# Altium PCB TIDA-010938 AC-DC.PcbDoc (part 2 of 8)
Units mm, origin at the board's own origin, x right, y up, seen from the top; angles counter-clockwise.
Board outline 280 x 180.15 mm, 4 copper layers (Top Layer, Layer 1, Layer 2, Bottom Layer), stack 1.787 mm thick; 723 components, 427 nets, 2244 pads, 2295 vias.
Unrouted connection lines stored in the file: 17.
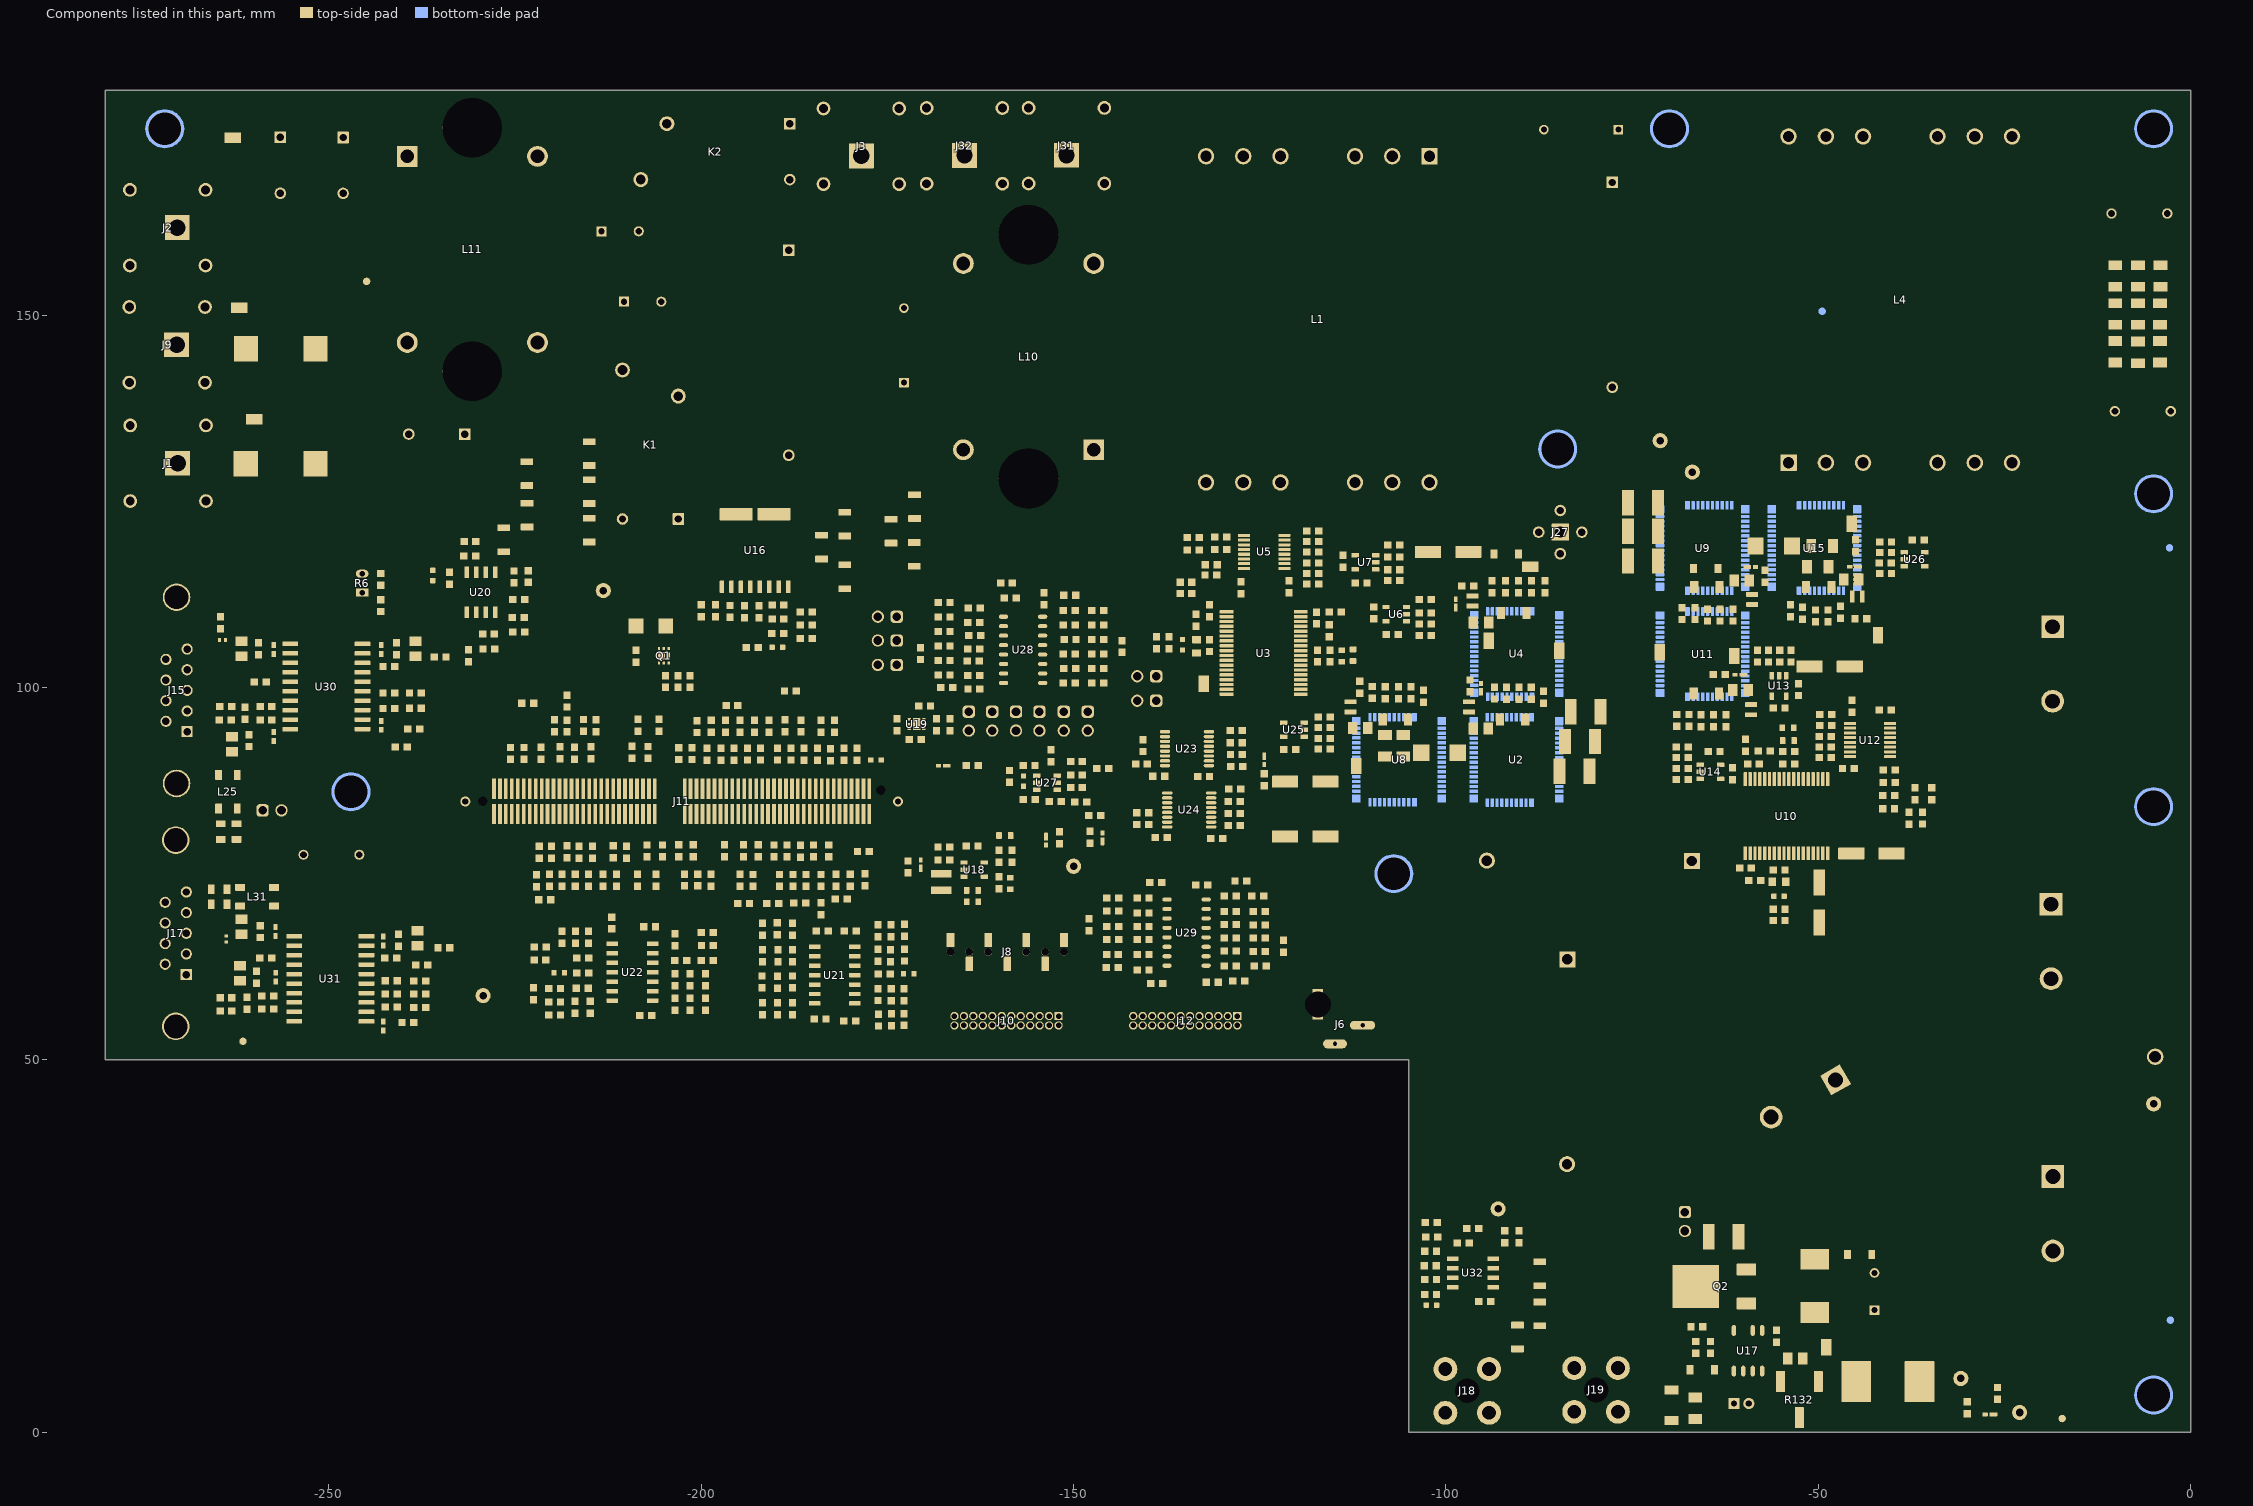
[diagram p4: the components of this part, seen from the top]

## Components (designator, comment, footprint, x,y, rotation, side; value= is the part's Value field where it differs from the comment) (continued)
R111 "TNPV12061M00BEEN" TNPV1206 -180.717,121.92 r270 top value=1.00Meg
R112 "TNPV12061M00BEEN" TNPV1206 -183.825,118.847 r270 top value=1.00Meg
R113 "TNPV12061M00BEEN" TNPV1206 -180.717,114.859 r270 top value=1.00Meg
R114 "PTCEL13R600LBE" FP-PTCEL13R600LBE_RADIAL-MFG -210.867,161.239 r0 top value=60Ω
R115 "RC0603JR-075K6L" 0603 -45,119 r270 top value=5.6k
R116 "TNPV12061M00BEEN" TNPV1206 -215,131.4 r270 top value=1.00Meg
R117 "TNPV12061M00BEEN" TNPV1206 -215,126.3 r270 top value=1.00Meg
R118 "TNPV12061M00BEEN" TNPV1206 -215.033,121.132 r270 top value=1.00Meg
R119 "RT0603BRD077K32L" 0603 -174.55,63.975 r90 top value=7.32k
R120 "RG1608P-560-B-T5" 0603 -224.469,111.785 r0 top value=56
R121 "RG1608P-560-B-T5" 0603 -231.25,104.254 r270 top value=56
R122 "TNPV12061M00BEEN" TNPV1206 -171.345,124.282 r270 top value=1.00Meg
R123 "TNPV12061M00BEEN" TNPV1206 -174.494,120.98 r270 top value=1.00Meg
R124 "TNPV12061M00BEEN" TNPV1206 -171.386,117.856 r270 top value=1.00Meg
R125 "RG1608P-103-B-T5" 0603 -237.5,62.75 r0 top value=10.0k
R126 "RG1608P-103-B-T5" 0603 -258.448,63.698 r0 top value=10.0k
R127 "TNPV12061M00BEEN" TNPV1206 -223.4,128.7 r270 top value=1.00Meg
R128 "TNPV12061M00BEEN" TNPV1206 -223.364,123.139 r270 top value=1.00Meg
R129 "TNPV12061M00BEEN" TNPV1206 -226.513,119.837 r270 top value=1.00Meg
R130 "RG1608P-103-B-T5" 0603 -231.022,119.58 r0 top value=10.0k
R131 "RG1608P-103-B-T5" 0603 -228.539,107.185 r0 top value=10.0k
R132 "3269W-1-104LF" FP-3269W-1-104LF_SMD-MFG -52.553,4.401 r180 top
R133 "RG1608P-103-B-T5" 0603 -101.914,26.251 r0 top value=10.0k
R134 "RG1608P-560-B-T5" 0603 -96.43,27.381 r180 top value=56
R135 "RG1608P-103-B-T5" 0603 -101.99,28.194 r180 top value=10.0k
R136 "RT0603BRD077K32L" 0603 -221.625,63.4 r180 top value=7.32k
R137 "RT0603BRD077K32L" 0603 -172.7,64.075 r270 top value=7.32k
R138 "RT0603BRD077K32L" 0603 -172.7,67.4 r270 top value=7.32k
R139 "RT0603BRD077K32L" 0603 -221.597,65.173 r0 top value=7.32k
R140 "RG1608P-560-B-T5" 0603 -180.019,55.22 r180 top value=56
R141 "RG1608P-560-B-T5" 0603 -211.998,68.379 r90 top value=56
R142 "RT0603BRD077K32L" 0603 -174.525,67.35 r270 top value=7.32k
R143 "RT0603BRD077K32L" 0603 -218.657,66.476 r270 top value=7.32k
R144 "RG1608P-560-B-T5" 0603 -163.242,106.985 r180 top value=56
R145 "RT0603BRD077K32L" 0603 -216.879,66.476 r270 top value=7.32k
R146 "RG1608P-560-B-T5" 0603 -163.458,103.556 r180 top value=56
R147 "RG1608P-103-B-T5" 0603 -219.673,59.576 r180 top value=10.0k
R148 "RG1608P-560-B-T5" 0603 -163.369,99.797 r180 top value=56
R149 "RG1608P-103-B-T5" 0603 -222.5,58.894 r270 top value=10.0k
R150 "RG1608P-560-B-T5" 0603 -179.968,67.302 r180 top value=56
R151 "RG1608P-560-B-T5" 0603 -219.673,56.02 r180 top value=56
R152 "RG1608P-560-B-T5" 0603 -159,114 r180 top value=56
R153 "RG1608P-103-B-T5" 0603 -219.673,57.798 r180 top value=10.0k
R154 "RG1608P-560-B-T5" 0603 -150.529,102.565 r0 top value=56
R155 "RG1608P-103-B-T5" 0603 -216.912,57.078 r270 top value=10.0k
R156 "RT0603BRD077K32L" 0603 -201.467,60.78 r90 top value=7.32k
R157 "RG1608P-103-B-T5" 0603 -189.675,63.975 r270 top value=10.0k
R158 "RG1608P-103-B-T5" 0603 -191.769,63.981 r90 top value=10.0k
R159 "RT0603BRD077K32L" 0603 -199.435,60.78 r270 top value=7.32k
R160 "RG1608P-560-B-T5" 0603 -183.74,67.3 r0 top value=56
R161 "RG1608P-560-B-T5" 0603 -207.426,55.933 r180 top value=56
R162 "RG1608P-103-B-T5" 0603 -191.769,67.537 r90 top value=10.0k
R163 "RT0603BRD077K32L" 0603 -199.435,57.478 r90 top value=7.32k
R164 "RG1608P-103-B-T5" 0603 -189.775,67.6 r90 top value=10.0k
R165 "RT0603BRD077K32L" 0603 -201.467,57.478 r90 top value=7.32k
R166 "RG1608P-103-B-T5" 0603 -199.143,65.352 r180 top value=10.0k
R167 "RG1608P-103-B-T5" 0603 -189.725,60.425 r270 top value=10.0k
R168 "RG1608P-103-B-T5" 0603 -191.802,60.467 r90 top value=10.0k
R169 "RG1608P-560-B-T5" 0603 -184.032,55.472 r0 top value=56
R170 "RG1608P-560-B-T5" 0603 -203.499,66.114 r90 top value=56
R171 "RG1608P-103-B-T5" 0603 -191.769,56.869 r270 top value=10.0k
R172 "RG1608P-103-B-T5" 0603 -199.181,63.32 r0 top value=10.0k
R173 "RG1608P-103-B-T5" 0603 -189.737,56.869 r270 top value=10.0k
R174 "RCS06030000Z0EA" 0603 -223.787,91.139 r90 top value=0
R175 "RG1608P-560-B-T5" 0603 -150.466,106.426 r0 top value=56
R176 "RCS06030000Z0EA" 0603 -215.8,94.9 r270 top value=0
R177 "RCS06030000Z0EA" 0603 -128.15,94.225 r180 top value=0
R178 "RCS06030000Z0EA" 0603 -216.975,91.175 r270 top value=0
R179 "RCS06030000Z0EA" 0603 -221.501,91.177 r90 top value=0
R180 "RCS06030000Z0EA" 0603 -218.025,94.825 r270 top value=0
R181 "RCS06030000Z0EA" 0603 -218.95,91.225 r270 top value=0
R182 "RCS06030000Z0EA" 0603 -220.375,74.1 r270 top value=0
R183 "RCS06030000Z0EA" 0603 -220.075,77.9 r270 top value=0
R184 "RCS06030000Z0EA" 0603 -218.025,77.925 r270 top value=0
R185 "ERJ-8ENF1693V" 1206 -4.155,150.146 r270 top value=169k
R186 "RCS06030000Z0EA" 0603 -215.118,74.129 r90 top value=0
R187 "RCS06030000Z0EA" 0603 -214.585,77.901 r90 top value=0
R188 "RCS06030000Z0EA" 0603 -213.153,74.116 r90 top value=0
R189 "RCS06030000Z0EA" 0603 -211.791,77.939 r90 top value=0
R190 "RCS06030000Z0EA" 0603 -208.55,74.125 r90 top value=0
R191 "RCS06030000Z0EA" 0603 -207.1,91.275 r90 top value=0
R192 "RCS06030000Z0EA" 0603 -207.244,78.051 r90 top value=0
R193 "RCS06030000Z0EA" 0603 -205.65,94.925 r90 top value=0
R194 "RCS06030000Z0EA" 0603 -209.25,91.3 r270 top value=0
R195 "RCS06030000Z0EA" 0603 -201.05,78.075 r270 top value=0
R196 "RCS06030000Z0EA" 0603 -208.45,94.925 r270 top value=0
R197 "RCS06030000Z0EA" 0603 -200.45,74.15 r270 top value=0
R198 "RCS06030000Z0EA" 0603 -206.05,74.125 r90 top value=0
R199 "RCS06030000Z0EA" 0603 -205.2,78.05 r90 top value=0
R200 "RCS06030000Z0EA" 0603 -203,78.075 r90 top value=0
R201 "RCS06030000Z0EA" 0603 -202.225,74.15 r90 top value=0
R202 "RCS06030000Z0EA" 0603 -128.35,86.35 r180 top value=0
R203 "RCS06030000Z0EA" 0603 -198.69,74.125 r90 top value=0
R204 "RCS06030000Z0EA" 0603 -201.219,91.126 r90 top value=0
R205 "RCS06030000Z0EA" 0603 -196.83,78.089 r90 top value=0
R206 "RCS06030000Z0EA" 0603 -198.641,94.798 r90 top value=0
R207 "RCS06030000Z0EA" 0603 -197.338,91.026 r90 top value=0
R208 "RCS06030000Z0EA" 0603 -196.699,94.776 r90 top value=0
R209 "RCS06030000Z0EA" 0603 -195.56,91.026 r90 top value=0
R210 "RCS06030000Z0EA" 0603 -194.325,78.1 r90 top value=0
R211 "RCS06030000Z0EA" 0603 -194.758,94.776 r90 top value=0
R212 "RCS06030000Z0EA" 0603 -193.02,74.091 r90 top value=0
R213 "RCS06030000Z0EA" 0603 -193.782,91.064 r90 top value=0
R214 "RCS06030000Z0EA" 0603 -192.325,78.1 r90 top value=0
R215 "RCS06030000Z0EA" 0603 -192.816,94.798 r90 top value=0
R216 "RCS06030000Z0EA" 0603 -192.004,91.064 r90 top value=0
R217 "RCS06030000Z0EA" 0603 -190.226,78.051 r90 top value=0
R218 "RCS06030000Z0EA" 0603 -190.875,94.775 r90 top value=0
R219 "RCS06030000Z0EA" 0603 -189.464,74.091 r90 top value=0
R220 "RCS06030000Z0EA" 0603 -189.718,91.064 r90 top value=0
R221 "RCS06030000Z0EA" 0603 -188.448,78.051 r90 top value=0
R222 "RCS06030000Z0EA" 0603 -188.75,94.85 r90 top value=0
R223 "RCS06030000Z0EA" 0603 -187.686,74.091 r90 top value=0
R224 "RCS06030000Z0EA" 0603 -187.94,91.064 r90 top value=0
R225 "RCS06030000Z0EA" 0603 -186.67,78.013 r90 top value=0
R226 "RCS06030000Z0EA" 0603 -186.609,94.825 r90 top value=0
R227 "RCS06030000Z0EA" 0603 -185.908,74.091 r90 top value=0
R228 "RCS06030000Z0EA" 0603 -186.162,91.026 r90 top value=0
R229 "RCS06030000Z0EA" 0603 -184.892,78.051 r90 top value=0
R230 "RCS06030000Z0EA" 0603 -184.384,91.026 r90 top value=0
R231 "RCS06030000Z0EA" 0603 -183.876,74.091 r90 top value=0
R232 "RCS06030000Z0EA" 0603 -183.876,94.798 r90 top value=0
R233 "RCS06030000Z0EA" 0603 -182.86,78.051 r90 top value=0
R234 "RCS06030000Z0EA" 0603 -182.606,90.988 r90 top value=0
R235 "ERJ-8ENF1693V" 1206 -7.108,150.146 r270 top value=169k
R236 "RCS06030000Z0EA" 0603 -182.098,94.798 r90 top value=0
R237 "RG1608P-103-B-T5" 0603 -102.8,107 r180 top value=10.0k
R238 "RG1608P-103-B-T5" 0603 -102.071,24.311 r180 top value=10.0k
R239 "RG1608P-103-B-T5" 0603 -102.091,22.37 r180 top value=10.0k
R240 "RCS06030000Z0EA" 0603 -127.525,74.025 r180 top value=0
R241 "RCS06030000Z0EA" 0603 -150.5,112.375 r180 top value=0
R242 "RCS06030000Z0EA" 0603 -121.8,65.275 r270 top value=0
R243 "RCS06030000Z0EA" 0603 -143.5,105.5 r270 top value=0
R244 "RCS06030000Z0EA" 0603 -127.827,60.598 r180 top value=0
R245 "RCS06030000Z0EA" 0603 -158.5,112 r180 top value=0
R246 "RCS06030000Z0EA" 0603 -138.825,60.25 r180 top value=0
R247 "RCS06030000Z0EA" 0603 -167,100 r180 top value=0
R248 "RCS06030000Z0EA" 0603 -147.9,68.125 r270 top value=0
R249 "RCS06030000Z0EA" 0603 -170.55,104.55 r270 top value=0
R250 "RCS06030000Z0EA" 0603 -138.975,73.825 r0 top value=0
R252 "RG1608P-103-B-T5" 0603 -149.6,86.55 r180 top value=10.0k
R253 "RG1608P-103-B-T5" 0603 -128.983,72.001 r180 top value=10.0k
R254 "RG1608P-103-B-T5" 0603 -150.553,110.312 r180 top value=10.0k
R256 "RG1608P-103-B-T5" 0603 -149.6,88.25 r180 top value=10.0k
R259 "RG1608P-560-B-T5" 0603 -140.667,69.715 r180 top value=56
R260 "RG1608P-560-B-T5" 0603 -167.385,109.463 r0 top value=56
R263 "RG1608P-560-B-T5" 0603 -144.731,71.747 r0 top value=56
R264 "RG1608P-560-B-T5" 0603 -140.667,66.159 r180 top value=56
R265 "RG1608P-560-B-T5" 0603 -167.385,105.58 r0 top value=56
R267 "RG1608P-560-B-T5" 0603 -144.731,67.937 r0 top value=56
R268 "RG1608P-560-B-T5" 0603 -167.385,101.697 r0 top value=56
R270 "RG1608P-560-B-T5" 0603 -144.769,64.127 r0 top value=56
R272 "RG1608P-560-B-T5" 0603 -140.667,62.095 r180 top value=56
R273 "RG1608P-560-B-T5" 0603 -146.743,100.602 r180 top value=56
R274 "RG1608P-560-B-T5" 0603 -124.935,62.603 r180 top value=56
R276 "RG1608P-560-B-T5" 0603 -146.743,104.485 r180 top value=56
R278 "RG1608P-560-B-T5" 0603 -125.049,66.344 r180 top value=56
R279 "RG1608P-560-B-T5" 0603 -131.4,60.425 r0 top value=56
R280 "RT0603DRE0759R7L" 0603 -258.41,95.645 r0 top value=59.7
R281 "RG1608P-560-B-T5" 0603 -146.743,108.368 r180 top value=56
R282 "RG1608P-560-B-T5" 0603 -125.049,69.9 r180 top value=56
R284 "RG1608P-560-B-T5" 0603 -128.983,64.602 r0 top value=56
R286 "RG1608P-560-B-T5" 0603 -128.983,68.158 r0 top value=56
R287 "RT0603DRE0759R7L" 0603 -258.41,97.423 r180 top value=59.7
R288 "RT0603DRE0759R7L" 0603 -258.152,56.82 r0 top value=59.7
R289 "RT0603DRE0759R7L" 0603 -258.19,58.598 r180 top value=59.7
R290 "ERJ-8ENF1693V" 1206 -10.156,150.146 r270 top value=169k
R291 "ERJ-8ENF1693V" 1206 -10.156,155.226 r270 top value=169k
R297 "RG1608P-103-B-T5" 0603 -146.743,110.31 r180 top value=10.0k
R298 "RG1608P-103-B-T5" 0603 -146.743,106.427 r180 top value=10.0k
R299 "RG1608P-103-B-T5" 0603 -146.743,102.544 r180 top value=10.0k
R300 "RG1608P-103-B-T5" 0603 -167.385,103.639 r0 top value=10.0k
R301 "RG1608P-103-B-T5" 0603 -167.385,107.522 r0 top value=10.0k
R302 "RG1608P-103-B-T5" 0603 -167.385,111.405 r0 top value=10.0k
R303 "RG1608P-103-B-T5" 0603 -125.289,72.001 r180 top value=10.0k
R304 "RG1608P-103-B-T5" 0603 -125.049,68.122 r180 top value=10.0k
R305 "RG1608P-103-B-T5" 0603 -125.049,64.566 r180 top value=10.0k
R306 "RG1608P-103-B-T5" 0603 -144.807,62.386 r0 top value=10.0k
R307 "RG1608P-103-B-T5" 0603 -144.731,66.159 r0 top value=10.0k
R308 "RG1608P-103-B-T5" 0603 -144.731,69.969 r0 top value=10.0k
R310 "RG1608P-103-B-T5" 0603 -241.9,102.794 r0 top value=10.0k
R311 "RG1608P-560-B-T5" 0603 -238.344,97.206 r180 top value=56
R312 "RMCF0805ZT0R00" FP-RMCF0805ZT0R00_0805-MFG -262.375,80.65 r270 top
R314 "RG1608P-560-B-T5" 0603 -238.344,99.238 r180 top value=56
R316 "RMCF0805ZT0R00" FP-RMCF0805ZT0R00_0805-MFG -264.475,80.65 r270 top
R318 "RG1608P-103-B-T5" 0603 -241.642,63.678 r0 top value=10.0k
R319 "RG1608P-560-B-T5" 0603 -241.604,58.852 r180 top value=56
R320 "RG1608P-560-B-T5" 0603 -241.604,60.63 r180 top value=56
R321 "RMCF0805ZT0R00" FP-RMCF0805ZT0R00_0805-MFG -264.7,70.9 r180 top
R323 "RG1608P-560-B-T5" 0603 -241.604,57.074 r180 top value=56
R325 "RMCF0805ZT0R00" FP-RMCF0805ZT0R00_0805-MFG -264.7,72.9 r180 top
R326 "ERJ-8ENF1693V" 1206 -4.06,155.226 r270 top value=169k
R327 "ERJ-8ENF1693V" 1206 -7.108,155.226 r270 top value=169k
R328 "RG1608P-103-B-T5" 0603 -102.8,111.8 r180 top value=10.0k
R329 "RG1608P-103-B-T5" 0603 -107,114.35 r180 top value=10.0k
R330 "RG1608P-103-B-T5" 0603 -107,119.125 r180 top value=10.0k
R331 "RG1608P-103-B-T5" 0603 -53.69,104.221 r270 top value=10.0k
R332 "RG1608P-103-B-T5" 0603 -58.19,104.221 r270 top value=10.0k
R335 "RG1608P-103-B-T5" 0603 -116.35,91.725 r180 top value=10.0k
R336 "RG1608P-103-B-T5" 0603 -40.99,119.521 r0 top value=10.0k
R337 "RG1608P-103-B-T5" 0603 -116.35,96.025 r180 top value=10.0k
R338 "RG1608P-103-B-T5" 0603 -40.99,115.321 r0 top value=10.0k
TP1 "S2751-46R" Harwin_S2751-46R -71.29,104.721 r90 top
TP2 "5001" Keystone5001 -4.994,44.094 r90 top
TP3 "5001" Keystone5001 -22.987,2.667 r90 top
TP4 "S2751-46R" Harwin_S2751-46R -262,151 r180 top
TP5 "S2751-46R" Harwin_S2751-46R -84.775,104.952 r90 top
TP6 "S2751-46R" Harwin_S2751-46R -262.886,173.787 r180 top
TP7 "S2751-46R" Harwin_S2751-46R -260,136 r180 top
TP8 "5003" Keystone5003 -30.89,7.237 r90 top
TP9 "S2751-46R" Harwin_S2751-46R -88.7,116.2 r180 top
TP10 "5117" Keystone5117 -66.934,128.905 r90 top
TP11 "S2751-46R" Harwin_S2751-46R -45.5,122 r90 top
TP12 "5001" Keystone5001 -93,30 r90 top
TP13 "5005" Keystone5005 -4.792,50.419 r90 top
TP14 "5001" Keystone5001 -71.243,133.121 r90 top
TP15 "5001" Keystone5001 -149.983,75.997 r90 top
TP16 "S2751-46R" Harwin_S2751-46R -112.018,89.452 r90 top
TP17 "S2751-46R" Harwin_S2751-46R -94.25,106.25 r270 top
TP18 "S2751-46R" Harwin_S2751-46R -61.29,104.221 r90 top
TP19 "5001" Keystone5001 -213.128,113.005 r90 top
TP20 "5001" Keystone5001 -229.257,58.623 r90 top
TP21 "S2751-46R" Harwin_S2751-46R -132.5,100.5 r90 top
TP22 "S2751-46R" Harwin_S2751-46R -42,107 r90 top
TP23 "S2751-46R" Harwin_S2751-46R -48.971,11.399 r90 top
U2 "LMG3522R030Q" RQS0052C-C01-MFG -90.535,90.275 r180 bottom
U3 "UCC14131QDWNRQ1" DWJ0036A-MFG -124.475,104.625 r0 top
U4 "LMG3522R030Q" RQS0052C-C01-MFG -90.5,104.5 r180 bottom
U5 "ISO7762FQDBQRQ1" DBQ0016A-MFG -124.4,118.2 r180 top
U6 "SN74LVC1G08DBVT" DBV0005A_N -106.675,109.85 r180 top
U7 "SN74LVC1G08DBVT" DBV0005A_N -110.825,116.8 r180 top
U8 "LMG3522R030Q" RQS0052C-C01-MFG -106.293,90.3 r180 bottom
U9 "LMG3522R030Q" RQS0052C-C01-MFG -65.54,118.721 r0 bottom
U10 "UCC14131QDWNRQ1" DWJ0036A-MFG -54.29,82.721 r90 top
U11 "LMG3522R030Q" RQS0052C-C01-MFG -65.54,104.471 r0 bottom
U12 "ISO7762FQDBQRQ1" DBQ0016A-MFG -43.065,92.943 r0 top
U13 "SN74LVC1G08DBVT" DBV0005A_N -55.29,100.221 r270 top
U14 "SN74LVC1G08DBVT" DBV0005A_N -64.515,88.671 r0 top
U15 "LMG3522R030Q" RQS0052C-C01-MFG -50.54,118.721 r0 bottom
U16 "TMCS1123B1QDVGR" DVG0010A-MFG -192.75,118.391 r270 top
U17 "UCC28710DR" D0007A_N -59.455,10.951 r90 top
U18 "TPS560200DBVR" DBV0005A_N -163.333,75.549 r0 top
U19 "TLV75533PDRVR" DRV0006A -171.06,95.076 r0 top
U20 "OPA2388IDR" D0008A-MFG -229.55,112.775 r90 top
U21 "OPA4388IDR" D0014A-MFG -182.047,61.387 r180 top
U22 "OPA4388IDR" D0014A-MFG -209.204,61.775 r0 top
U23 "SN74HC251PW" PW0016A_N -134.775,91.775 r180 top
U24 "SN74HC251PW" PW0016A_N -134.475,83.55 r180 top
U25 "SN74LVC1G08DBVT" DBV0005A_N -120.426,94.329 r180 top
U26 "SN74LVC1G08DBVT" DBV0005A_N -37.09,117.221 r0 top
U27 "SN74LVC2G34DBVR" DBV0006A_N -153.575,87.225 r180 top
U28 "SN74HC365D" D0016A_L -156.775,105.05 r0 top
U29 "SN74HC365D" D0016A_L -134.825,67.09 r0 top
U30 "ISOW1044DFM" DFM0020A-MFG -250.306,100.127 r180 top
U31 "ISOW1412DFM" DFM0020A-MFG -249.77,60.884 r180 top
U32 "OPA2388IDR" D0008A-MFG -96.375,21.4 r180 top
ZZ1 "This Assembly Note is for PCB labels only" AssemblyNoteLabel -286.335,-76 r0 top
ZZ2 "These assemblies are ESD sensitive, ESD precautions shall be observed." AssemblyNote -223.585,-72.25 r0 top
ZZ3 "These assemblies must be clean and free from flux and all contaminants. Use of no clean flux is not acceptable." AssemblyNote 1.65,4.125 r90 top
ZZ4 "These assemblies must comply with workmanship standards IPC-A-610 Class 2, unless otherwise specified." AssemblyNote -254.835,-64.75 r0 top

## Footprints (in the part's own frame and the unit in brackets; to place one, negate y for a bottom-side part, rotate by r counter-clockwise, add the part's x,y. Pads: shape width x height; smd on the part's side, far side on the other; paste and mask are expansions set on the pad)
0402 [mm] "0402 from SM-752 data"
  rect 0.8x0.6 smd: 1(-0.6,0) 2(0.6,0)
  silkscreen extent -1.22,-0.52 1.22,0.52, body extent -0.55,-0.3 0.55,0.3, height 0.6
0603 [mm] "0603 from SM-752 data"
  rect 1x0.95 smd: 1(-0.8,0) 2(0.8,0)
  silkscreen extent -1.52,-0.69 1.52,0.69, body extent -0.87,-0.47 0.87,0.47, height 1
0704 [mm] "Murata"
  rrect11% 1x1.2 smd: 1(-0.9,0) 2(0.9,0)
  silkscreen extent -0.25,-0.77 0.25,0.8, body extent -0.95,-0.55 0.95,0.55, height 0.8
0805_HV [mil] "0805 with 30mil clearance between pads"
  rect 50x63 smd: 1(-40,0) 2(40,0)
  silkscreen extent -74,-40 74,40, body extent -43,-29 43,29, height 57
1206 [mm] "1206 from SM-752 data"
  rect 1.3x1.85 smd: 1(-1.45,0) 2(1.45,0)
  silkscreen extent -2.4,-1.21 2.4,1.21, body extent -1.7,-0.9 1.7,0.9, height 1.35
1206_180 [mm] "1206_180"
  rect 1.1x1.6 smd: 1(-1.7,0) 2(1.7,0)
  silkscreen extent -0.9,-1 0.9,1, body extent -1.75,-0.95 1.75,0.95, height 1.8
1812_254 [mm] "SMD, 2-Leads, Body 4.8x3.4mm"
  rect 1.6x3.4 smd: 1(-2,0) 2(2,0)
  silkscreen extent -0.8,-1.7 0.8,1.7, body extent -2.4,-1.7 2.4,1.7, height 2.54
AssemblyNote [mm] "Assembly Note"
AssemblyNoteLabel [mm] "Assembly Note for PCB Labels"
CAPPR2-5x11 [mm] "Capacitor, Electrolytic, Radial; Body 5 x 11 mm (Dia.xH typ); Pin Spacing 2 mm (typ)"
  rrect7% 1.5x1.5 hole 0.85: 1(-1,0)
  round 1.5 hole 0.85: 2(1,0)
  silkscreen extent -2.5,-2.5 2.5,2.5, body extent -2.53,-2.53 2.53,2.52, height 11.29
CE_Mark_5mm [mm] "Minimum text height for CE Mark"
  silkscreen extent -3.5,-2.5 3.5,2.5
CK45_1250x600x1650 [mm] "TH, 2-Leads, Dia 12.5mm, Pin Spacing 7.5mm"
  round 1.35 hole 0.9: 1(-3.75,0) 2(3.75,0)
  body extent -6.25,-3 6.25,3, height 16.25
controlCARD-120HSEC [mm] "Pads are not numbered according to Samtec datasheet."
  rect 0.5x2.724 smd: 1(-23.357,-1.678) 2(-23.357,1.722) 3(-22.557,-1.678) 4(-22.557,1.722) 5(-21.757,-1.678) 6(-21.757,1.722) 7(-20.957,-1.678) 8(-20.957,1.722) 9(-20.157,-1.678) 10(-20.157,1.722) 11(-19.357,-1.678) 12(-19.357,1.722) 13(-18.557,-1.678) 14(-18.557,1.722) 15(-17.757,-1.678) 16(-17.757,1.722) 17(-16.957,-1.678) 18(-16.957,1.722) 19(-16.157,-1.678) 20(-16.157,1.722) 21(-15.357,-1.678) 22(-15.357,1.722) 23(-14.557,-1.678) 24(-14.557,1.722) 25(-13.757,-1.678) 26(-13.757,1.722) 27(-12.957,-1.678) 28(-12.957,1.722) 29(-12.157,-1.678) 30(-12.157,1.722) 31(-11.357,-1.678) 32(-11.357,1.722) 33(-10.557,-1.678) 34(-10.557,1.722) 35(-9.757,-1.678) 36(-9.757,1.722) 37(-8.957,-1.678) 38(-8.957,1.722) 39(-8.157,-1.678) 40(-8.157,1.722) 41(-7.357,-1.678) 42(-7.357,1.722) 43(-6.557,-1.678) 44(-6.557,1.722) 45(-5.757,-1.678) 46(-5.757,1.722) 47(-4.957,-1.678) 48(-4.957,1.722) 49(-4.157,-1.678) 50(-4.157,1.722) 51(-3.357,-1.678) 52(-3.357,1.722) 53(-2.557,-1.678) 54(-2.557,1.722) 55(-1.757,-1.678) 56(-1.757,1.722) 57(2.243,-1.678) 58(2.243,1.722) 59(3.043,-1.678) 60(3.043,1.722) 61(3.843,-1.678) 62(3.843,1.722) 63(4.643,-1.678) 64(4.643,1.722) 65(5.443,-1.678) 66(5.443,1.722) 67(6.243,-1.678) 68(6.243,1.722) 69(7.043,-1.678) 70(7.043,1.722) 71(7.843,-1.678) 72(7.843,1.722) 73(8.643,-1.678) 74(8.643,1.722) 75(9.443,-1.678) 76(9.443,1.722) 77(10.243,-1.678) 78(10.243,1.722) 79(11.043,-1.678) 80(11.043,1.722) 81(11.843,-1.678) 82(11.843,1.722) 83(12.643,-1.678) 84(12.643,1.722) 85(13.443,-1.678) 86(13.443,1.722) 87(14.243,-1.678) 88(14.243,1.722) 89(15.043,-1.678) 90(15.043,1.722) 91(15.843,-1.678) 92(15.843,1.722) 93(16.643,-1.678) 94(16.643,1.722) 95(17.443,-1.678) 96(17.443,1.722) 97(18.243,-1.678) 98(18.243,1.722) 99(19.043,-1.678) 100(19.043,1.722) 101(19.843,-1.678) 102(19.843,1.722) 103(20.643,-1.678) 104(20.643,1.722) 105(21.443,-1.678) 106(21.443,1.722) 107(22.243,-1.678) 108(22.243,1.722) 109(23.043,-1.678) 110(23.043,1.722) 111(23.843,-1.678) 112(23.843,1.722) 113(24.643,-1.678) 114(24.643,1.722) 115(25.443,-1.678) 116(25.443,1.722) 117(26.243,-1.678) 118(26.243,1.722) 119(27.043,-1.678) 120(27.043,1.722)
  round 0.025 hole 1.27 unplated mask+0.876: 181(-24.857,0.022) 182(28.543,1.522)
  round 1.348 hole 0.84: 185(-27.207,0.022) 186(30.893,0.022)
  silkscreen extent -32.11,-3.86 35.8,3.9, body extent -31.75,-3.48 35.3,3.52, height 12.35
D0007A_N [mm] "SOIC, 7-Leads, Body 4.9x3.9mm, Pitch 1.27mm, IPC Medium Density"
  oval 1.45x0.6 smd: 1(-2.725,1.905) 2(-2.725,0.635) 3(-2.725,-0.635) 4(-2.725,-1.905) 5(2.725,-1.905) 6(2.725,-0.635) 8(2.725,1.905)
  silkscreen extent -3.32,-2.5 1.1,2.52, body extent -3.01,-2.45 3.01,2.45, height 1.75
D0008A-MFG [mm]
  rrect17% 1.55x0.6 smd paste+0 mask+0: 1(-2.7,1.905) 2(-2.7,0.635) 3(-2.7,-0.635) 4(-2.7,-1.905) 5(2.7,-1.905) 6(2.7,-0.635) 7(2.7,0.635) 8(2.7,1.905)
  silkscreen extent -4.17,-2.5 1.5,2.5, body extent -3.57,-2.75 3.57,2.75, height 0.25
D0014A-MFG [mm]
  rrect17% 1.55x0.6 smd paste-1000 mask+0: 1(-2.7,3.81) 2(-2.7,2.54) 3(-2.7,1.27) 4(-2.7,0) 5(-2.7,-1.27) 6(-2.7,-2.54) 7(-2.7,-3.81) 8(2.7,-3.81) 9(2.7,-2.54) 10(2.7,-1.27) 11(2.7,0) 12(2.7,1.27) 13(2.7,2.54) 14(2.7,3.81)
  silkscreen extent -4.15,-4.38 1.55,4.38, body extent -3.57,-4.62 3.57,4.62, height 0.25
D0016A_L [mm] "SOIC, 16-Leads, Body 9.9x3.9mm, Pitch 1.27mm, IPC High Density"
  oval 1.25x0.55 smd: 1(-2.625,4.445) 2(-2.625,3.175) 3(-2.625,1.905) 4(-2.625,0.635) 5(-2.625,-0.635) 6(-2.625,-1.905) 7(-2.625,-3.175) 8(-2.625,-4.445) 9(2.625,-4.445) 10(2.625,-3.175) 11(2.625,-1.905) 12(2.625,-0.635) 13(2.625,0.635) 14(2.625,1.905) 15(2.625,3.175) 16(2.625,4.445)
  silkscreen extent -3.1,-5 0.9,5, body extent -3,-4.95 3,4.95, height 1.6
DBQ0016A-MFG [mm]
  rrect24% 1.6x0.41 smd paste+0 mask+0: 1(-2.7,2.222) 2(-2.7,1.587) 3(-2.7,0.952) 4(-2.7,0.317) 5(-2.7,-0.318) 6(-2.7,-0.953) 7(-2.7,-1.588) 8(-2.7,-2.223) 9(2.7,-2.222) 10(2.7,-1.587) 11(2.7,-0.952) 12(2.7,-0.317) 13(2.7,0.318) 14(2.7,0.953) 15(2.7,1.588) 16(2.7,2.223)
  silkscreen extent -4.18,-2.5 1.5,2.5, body extent -3.6,-2.75 3.6,2.75, height 0.25
DBV0005A_N [mm] "SOT23, 5-Leads, Body 2.9x1.6mm, Pitch 0.95mm, Lead Span 2.8mm, IPC Medium Density"
  rrect17% 1x0.6 smd: 1(-1.375,0.95) 2(-1.375,0) 3(-1.375,-0.95) 4(1.375,-0.95) 5(1.375,0.95)
  silkscreen extent -0.25,-1.55 0.25,1.55, body extent -1.42,-1.46 1.42,1.46, height 1.09
DBV0006A_N [mm] "SOT23, 6-Leads, Body 2.9x1.6mm, Pitch 0.95mm, Lead Span 2.8mm, IPC Medium Density"
  rrect17% 1x0.6 smd: 1(-1.375,0.95) 2(-1.375,0) 3(-1.375,-0.95) 4(1.375,-0.95) 5(1.375,0) 6(1.375,0.95)
  silkscreen extent -1.68,-1.55 0.5,1.55, body extent -1.42,-1.46 1.42,1.46, height 1.12
DFM0020A-MFG [mm]
  rrect17% 2.1x0.6 smd paste+0 mask+0: 1(-4.85,5.715) 2(-4.85,4.445) 3(-4.85,3.175) 4(-4.85,1.905) 5(-4.85,0.635) 6(-4.85,-0.635) 7(-4.85,-1.905) 8(-4.85,-3.175) 9(-4.85,-4.445) 10(-4.85,-5.715) 11(4.85,-5.715) 12(4.85,-4.445) 13(4.85,-3.175) 14(4.85,-1.905) 15(4.85,-0.635) 16(4.85,0.635) 17(4.85,1.905) 18(4.85,3.175) 19(4.85,4.445) 20(4.85,5.715)
  silkscreen extent -6.58,-6.47 3.4,6.47, body extent -6,-6.72 6,6.72, height 0.25
DPAK [mm] "D-PAK, 3-Pads, Body 6.22x6.73mm (max), TO-252AA using nominal STEP model"
  rrect6% 2.6x1.6 smd: 1(-3.4,2.28) 3(-3.4,-2.28)
  rrect2% 6.2x5.8 smd paste-3: 2(3.4,0)
  body extent -3.86,-3.29 5.84,3.29, height 2.48
DRV0006A [mm] "SON, 6-Leads, Body 2x2mm, Pitch 0.65mm, Thermal Pad 1.6x1mm, TI Recommended"
  rrect33% 0.45x0.3 smd: 1(-0.975,0.65) 2(-0.975,0) 3(-0.975,-0.65) 4(0.975,-0.65) 5(0.975,0) 6(0.975,0.65)
  rrect14% 1x0.7 on Top Paste: 7(0,-0.45) 7(0,0.45)
  rrect10% 1x1.6 smd paste-0.5: 7(0,0)
  silkscreen extent -1.05,-1.2 1.05,1.2, body extent -1.05,-1.05 1.05,1.05, height 0.81
DVG0010A-MFG [mm]
  rrect6% 1.65x4.41 smd paste+0 mask+0: 1(-4.875,2.54) 2(-4.875,-2.54)
  rrect17% 1.65x0.6 smd paste+0 mask+0: 3(4.875,-4.445) 4(4.875,-3.175) 5(4.875,-1.905) 6(4.875,-0.635) 7(4.875,0.635) 8(4.875,1.905) 9(4.875,3.175) 10(4.875,4.445)
  silkscreen extent -6.35,-5.25 3.8,5.25, body extent -5.8,-5.5 5.8,5.5, height 0.25
DWJ0036A-MFG [mm]
  rrect22% 1.85x0.45 smd paste+0 mask+0: 1(-4.975,5.525) 2(-4.975,4.875) 3(-4.975,4.225) 4(-4.975,3.575) 5(-4.975,2.925) 6(-4.975,2.275) 7(-4.975,1.625) 8(-4.975,0.975) 9(-4.975,0.325) 10(-4.975,-0.325) 11(-4.975,-0.975) 12(-4.975,-1.625) 13(-4.975,-2.275) 14(-4.975,-2.925) 15(-4.975,-3.575) 16(-4.975,-4.225) 17(-4.975,-4.875) 18(-4.975,-5.525) 19(4.975,-5.525) 20(4.975,-4.875) 21(4.975,-4.225) 22(4.975,-3.575) 23(4.975,-2.925) 24(4.975,-2.275) 25(4.975,-1.625) 26(4.975,-0.975) 27(4.975,-0.325) 28(4.975,0.325) 29(4.975,0.975) 30(4.975,1.625) 31(4.975,2.275) 32(4.975,2.925) 33(4.975,3.575) 34(4.975,4.225) 35(4.975,4.875) 36(4.975,5.525)
  silkscreen extent -6.57,-6.47 3.8,6.47, body extent -6,-6.72 6,6.72, height 0.25
E_900x700x900 [mm] "TH, 2- Leads, Body 9x7mm, Pin Spacing 7.5mm"
  round 1.4 hole 0.9: 1(-3.75,0) 2(3.75,0)
  silkscreen extent -4.5,-3.5 4.5,3.5, body extent -4.49,-3.5 4.49,3.5, height 11.96
FCC_disclaimer [mm]
Fiducial10-20 [mm]
  round 1 smd mask+0.5: 1(0,0)
  Top Layer keep-out circle w1.178: c0,0 r0.5
FP-3269W-1-104LF_SMD-MFG [mm]
  rrect8% 1.19x2.79 smd paste+0 mask+0: 1(-2.54,-2.415) 2(0,2.415) 3(2.54,-2.415)
  silkscreen extent -3.43,-2.28 3.43,2.28, body extent -3.53,-3.91 3.53,3.91, height 0.25
FP-047708_PTH4-MFG [mm]
  rrect4% 2.8x2.8 hole 1.85 paste-2539.97 mask+0: AI(-12.5,-8.75)
  round 2.8 hole 1.85 paste-2539.97 mask+0: AII(12.5,-8.75) EI(-12.5,8.75) EII(12.5,8.75)
  rrect100% 2.5x8 hole 8 slot 2.5 at 0 deg unplated paste-2539.97 mask+0: ""(-16.35,0) ""(16.35,0)
  silkscreen extent -20,-12.2 20,11.5, body extent -20.1,-11.6 20.1,11.6, height 0.25
FP-145453_PTH12-MFG [mm]
  rrect5% 2.2x2.2 hole 1.5 paste-2539.97 mask+0: 1(-21.9,15)
  round 2.2 hole 1.5 paste-2539.97 mask+0: 2(-21.9,10) 3(-21.9,5) 4(-21.9,-5) 5(-21.9,-10) 6(-21.9,-15) 7(21.9,-15) 8(21.9,-10) 9(21.9,-5) 10(21.9,5) 11(21.9,10) 12(21.9,15)
  silkscreen extent -25.72,-25 25,25, body extent -26,-26 26,26, height 0.25
FP-9774015960R_ROUND_SPACER_6MM0-MFG#1 [mm]
  round 5.245 smd paste-1000 mask-1000: 1(0,0)
  round 4.4 hole 4.4 unplated paste-2539.97 mask+0: ""(0,0)
  silkscreen extent -4.15,-4.15 4.15,4.15, body extent -3,-3 3,3, height 1.6
FP-9774015960R_ROUND_SPACER_6MM0-MFG#2 [mm]
  round 5.245 smd paste-1000 mask-1000: 1(0,0)
  round 4.4 hole 4.4 unplated paste-2539.97 mask+0: ""(0,0)
  Top Layer circle w1.5: c0,0 r2.95
  silkscreen extent -4.15,-4.15 4.15,4.15, body extent -3,-3 3,3, height 1.6
FP-694106402002_CONN_PWR_10MM7_9MM0-MFG [mm]
  rrect7% 1.4x4.1 hole 3.5 slot 0.8 at 0 deg paste-2539.97 mask+0: 1(-3.5,1.15)
  rrect100% 3.2x1.2 hole 0.6 slot 2.6 at 0 deg paste-2539.97 mask+0: 2(-1.2,-4.15)
  rrect100% 3.4x1.2 hole 0.6 slot 2.8 at 0 deg paste-2539.97 mask+0: 3(2.5,-1.65)
  silkscreen extent -4.75,-5.5 4.75,5.5, body extent -4.85,-5.6 4.85,5.6, height 0.25
FP-ACT45B-101-2P-TL003_SMT_4MM5_3MM2-MFG [mm]
  rrect11% 1.35x0.9 smd paste+0 mask+0: 1(-2.275,1.25) 2(-2.275,-1.25) 3(2.275,-1.25) 4(2.275,1.25)
  silkscreen extent -3.62,-1.7 2.35,1.7, body extent -3.05,-1.8 3.05,1.8, height 0.25
FP-ALH82D161DD600_RADIAL-MFG [mm]
  rrect3% 3.05x3.05 hole 2 paste-2539.97 mask+0: 1(-5,0)
  round 3.05 hole 2 paste-2539.97 mask+0: 2(5,0)
  silkscreen extent -18,-18 18,18, body extent -18.1,-18.1 18.1,18.1, height 0.25
FP-BLM15EX331SN1D_0402-MFG [mm]
  rrect25% 0.4x0.5 smd paste+0 mask+0: 1(-0.4,0) 2(0.4,0)
  silkscreen extent -0.53,-0.63 0.52,0.63, body extent -0.7,-0.38 0.7,0.38, height 0.25
FP-C4AKOBU4500A31J_RADIAL-MFG [mm]
  rrect5% 2.15x2.15 hole 1.4 paste-2539.97 mask+0: 1(-13.75,0.05)
  round 2.15 hole 1.4 paste-2539.97 mask+0: 2(13.75,0)
  silkscreen extent -16.35,-9.85 16.35,9.85, body extent -16.45,-9.95 16.45,9.95, height 0.25
FP-CSD17318Q2_WSON6-MFG [mm]
  rrect33% 0.45x0.3 smd paste+0 mask+0: 1(-0.975,0.65) 2(-0.975,0) 3(-0.975,-0.65) 4(0.975,-0.65) 5(0.975,0) 6(0.975,0.65)
  rrect33% 0.75x0.3 smd paste-1000 mask+0: 7(0.095,-0.65)
  rrect11% 1x0.95 smd paste-1000 mask+0: 8(0,0.325)
  body extent -1.3,-1.15 1.3,1.15, height 0.25
FP-F862FY475K310ZV054_RADIAL-MFG [mm]
  rrect6% 1.55x1.55 hole 1 paste-2539.97 mask+0: 1(-13.75,0)
  round 1.55 hole 1 paste-2539.97 mask+0: 2(13.75,0)
  silkscreen extent -15.75,-11 15.75,11, body extent -15.85,-11.1 15.85,11.1, height 0.25
FP-FCR7350B_CONN_BANANA_JACK-MFG [mm]
  rrect3% 3.35x3.35 hole 2.2 paste-2539.97 mask+0: 1(11,0)
  round 1.85 hole 1.2 paste-2539.97 mask+0: 2(4.64,5.08) 3(14.8,5.08) 4(4.64,-5.08) 5(14.8,-5.08)
  silkscreen extent 5.94,-6.05 17.2,6.05, body extent -16.7,-6.15 16.7,6.15, height 0.25
FP-FCR7350G_CONN_BANANA_JACK-MFG [mm]
  rrect3% 3.35x3.35 hole 2.2 paste-2539.97 mask+0: 1(11,0)
  round 1.85 hole 1.2 paste-2539.97 mask+0: 2(4.64,5.08) 3(14.8,5.08) 4(4.64,-5.08) 5(14.8,-5.08)
  silkscreen extent -1.83,-6.05 17.2,6.05, body extent -16.7,-6.15 16.7,6.15, height 0.25
FP-FCR7350L_CONN_BANANA_JACK-MFG [mm]
  rrect3% 3.35x3.35 hole 2.2 paste-2539.97 mask+0: 1(11,0)
  round 1.85 hole 1.2 paste-2539.97 mask+0: 2(4.64,5.08) 3(14.8,5.08) 4(4.64,-5.08) 5(14.8,-5.08)
  silkscreen extent -1.83,-6.05 17.2,6.05, body extent -16.7,-6.15 16.7,6.15, height 0.25
"FP-G5PZ-1A-E DC12_PTH_RELAY_23MM8_10MM3-MFG" [mm]
  rrect6% 1.55x1.55 hole 1 paste-2539.97 mask+0: 1(-10,-3.75)
  round 2 hole 1.3 paste-2539.97 mask+0: 2(6.5,-3.75) 3(10,3.75)
  round 1.55 hole 1 paste-2539.97 mask+0: 4(-10,3.75)
  silkscreen extent -12.72,-5.25 12,5.25, body extent -12.1,-5.35 12.1,5.35, height 0.25
FP-GB02SLT12-214_DO-214AA-MFG [mm]
  rrect5% 2.16x2.26 smd paste+0 mask+0: 1(-2.45,0) 2(2.45,0)
  silkscreen extent -4.3,-1.97 2.28,1.97, body extent -3.63,-2.07 3.63,2.07, height 0.25
FP-IsoM5-275-B-L2_RADIAL-MFG [mm]
  rrect6% 1.55x1.55 hole 1 paste-2539.97 mask+0: 1(-3.75,0)
  round 1.55 hole 1 paste-2539.97 mask+0: 2(3.75,0)
  silkscreen extent -8.5,-3.15 8.5,3.15, body extent -8.6,-3.25 8.6,3.25, height 0.25
"FP-KG DELLS1.22-JGKH-24_0603-MFG" [mm]
  rrect20% 1.05x0.5 smd paste-1000 mask+0: 1(-0.47,0)
  rrect20% 0.7x0.5 smd paste-1000 mask+0: 2(0.645,0)
  silkscreen extent -1.67,-0.63 0.75,0.63, body extent -1.09,-0.55 1.09,0.55, height 0.25
FP-MH1608-601Y_0603-MFG [mm]
  rrect14% 0.7x0.7 smd paste+0 mask+0: 1(-0.7,0) 2(0.7,0)
  silkscreen extent -0.87,-0.8 0.87,0.8, body extent -1.15,-0.6 1.15,0.6, height 0.25
FP-MS0311_SMT_IND_12MM0_12MM0-MFG [mm]
  rrect3% 4x5.5 smd paste+0 mask+0: 1(-4.25,0) 2(4.25,0)
  silkscreen extent -6.25,-6.25 6.25,6.25, body extent -6.35,-6.35 6.35,6.35, height 0.25
FP-PK007-015_CONN_TESTCLIP-MFG [mm]
  rrect4% 2.3x2.3 hole 1.5 paste-2539.97 mask+0: 1(0,0)
  round 1.55 hole 1 paste-2539.97 mask+0: 2(0,2.9) 3(-2.9,0) 4(2.9,0) 5(0,-2.9)
  silkscreen extent -3.4,-3.4 3.4,3.4, body extent -3.77,-3.77 3.77,3.77, height 0.25
FP-PTCEL13R600LBE_RADIAL-MFG [mm]
  rrect7% 1.35x1.35 hole 0.85 paste-2539.97 mask+0: 1(-2.5,0)
  round 1.35 hole 0.85 paste-2539.97 mask+0: 2(2.5,0)
  silkscreen extent -6.75,-3.5 6.75,3.5, body extent -6.85,-3.6 6.85,3.6, height 0.25
FP-R413F168050T0K_RADIAL-MFG [mm]
  rrect8% 1.3x1.3 hole 0.8 paste-2539.97 mask+0: 1(-5,0)
  round 1.3 hole 0.8 paste-2539.97 mask+0: 2(5,0)
  silkscreen extent -6.65,-3.1 6.65,3.1, body extent -6.75,-3.2 6.75,3.2, height 0.25
FP-RMCF0805ZT0R00_0805-MFG [mm]
  rrect11% 0.9x1.3 smd paste+0 mask+0: 1(-1.05,0) 2(1.05,0)
  silkscreen extent -0.23,-0.67 0.23,0.67, body extent -1.6,-0.77 1.6,0.77, height 0.25
FP-SDEM20161T-4R7MS_SMD2-MFG [mm]
  rrect15% 0.65x1.6 smd paste+0 mask+0: 1(-0.675,0) 2(0.675,0)
  silkscreen extent -1.05,-1.22 1.05,1.2, body extent -1.15,-0.95 1.15,0.95, height 0.25
FP-SF-3812F2500T-2_SMD2-MFG [mm]
  rrect3% 3.25x3.43 smd paste+0 mask+0: 1(-4.675,0) 2(4.675,0)
  silkscreen extent -2.68,-1.65 2.68,1.65, body extent -6.4,-1.82 6.4,1.82, height 0.25
FP-SHF-112-01-L-D-TH_HDR24-MFG [mm]
  rrect9% 1.12x1.12 hole 0.74 paste-2539.97 mask+0: 1(-6.985,-0.89)
  round 1.12 hole 0.74 paste-2539.97 mask+0: 2(-6.985,0.38) 3(-5.715,-0.89) 4(-5.715,0.38) 5(-4.445,-0.89) 6(-4.445,0.38) 7(-3.175,-0.89) 8(-3.175,0.38) 9(-1.905,-0.89) 10(-1.905,0.38) 11(-0.635,-0.89) 12(-0.635,0.38) 13(0.635,-0.89) 14(0.635,0.38) 15(1.905,-0.89) 16(1.905,0.38) 17(3.175,-0.89) 18(3.175,0.38) 19(4.445,-0.89) 20(4.445,0.38) 21(5.715,-0.89) 22(5.715,0.38) 23(6.985,-0.89) 24(6.985,0.38)
  silkscreen extent -10.86,-3.46 10.86,2.86, body extent -10.96,-2.96 10.96,2.96, height 0.25
FP-SSM-107-L-SV-BE_HDR7-MFG [mm]
  rrect10% 1.02x1.905 smd paste+0 mask+0: 1(-7.62,-1.603) 2(-5.08,1.603) 3(-2.54,-1.603) 4(0,1.603) 5(2.54,-1.603) 6(5.08,1.603) 7(7.62,-1.603)
  round 1.02 hole 1.02 unplated paste-2539.97 mask+0: ""(-7.62,0) ""(-5.08,0) ""(-2.54,0) ""(0,0) ""(2.54,0) ""(5.08,0) ""(7.62,0)
  silkscreen extent -9.02,-3.27 9.02,1.34, body extent -9.12,-2.66 9.12,2.66, height 0.25
FP-ZRB18AR61E106ME01L_0603-MFG [mm]
  rrect13% 0.75x0.9 smd paste+0 mask+0: 1(-0.775,0) 2(0.775,0)
  silkscreen extent 0,-0.5 0,0.5, body extent -1.25,-0.6 1.25,0.6, height 0.25
FR_630X1120 [mm] "TH, 2-Leads, Dia 6.3mm, Lead Spacing 2.5mm"
  rect 1.3x1.3 hole 0.8: 1(-2.5,0)
  round 1.3 hole 0.8: 2(2.5,0)
  silkscreen extent -3.45,-3.45 3.45,3.45, body extent -3.37,-3.39 3.4,3.39, height 15.21
Harwin_S2751-46R [mm] "Test Point, SMT"
  rect 2.2x1.4 smd: 1(0,0)
  body extent -1,-0.6 1,0.6, height 1.4
IEC_HighVoltage_Small [mm]
  silkscreen extent -2.72,-2.24 2.72,2.47
IEC_HotSurface_Small [mm]
  silkscreen extent -2.72,-2.36 2.72,2.35
Keystone5001 [mil] "For Keystone 500x miniature loop terminals"
  round 80 hole 40: 1(0,0)
  silkscreen extent -52,-52 52,52, body extent -49,-49 49,49, height 182
Keystone5003 [mil] "For Keystone 500x miniature loop terminals"
  round 80 hole 40: 1(0,0)
  silkscreen extent -52,-52 52,52, body extent -49,-49 49,49, height 182
Keystone5005 [mil] "Keystone Compact loops"
  round 87 hole 63: 1(0,0)
  silkscreen extent -70,-70 70,70, body extent -63,-63 62,63, height 225
Keystone5117 [mil] "For Keystone 500x miniature loop terminals"
  round 80 hole 40: 1(0,0)
  silkscreen extent -52,-52 52,52, body extent -49,-49 49,49, height 182
Label_650x200 [mil] "Thermal Transfer Label"
  round 1 on Mech13: 0(0,0)
  silkscreen extent -325,-100 325,100, body extent -325,-100 325,100, height 1
LPG0002A-MFG [mm]
  rrect9% 1.07x1.7 hole 0.75 paste-2539.97 mask+0: 1(-1.27,0.21)
  rrect100% 1.07x1.7 hole 0.75 paste-2539.97 mask+0: 2(1.27,0.21)
  round 0.75 hole 0.75 unplated paste-2539.97 mask+0: ""(0,0.21)
  silkscreen extent -2.62,-0.81 0.36,0.2, body extent -2.15,-0.91 2.15,1.16, height 0.25
PW0016A_N [mm] "TSOP, 16-Leads, Body 5x4.4mm, Pitch 0.65mm, IPC Medium Density"
  oval 1.4x0.45 smd: 1(-2.95,2.275) 2(-2.95,1.625) 3(-2.95,0.975) 4(-2.95,0.325) 5(-2.95,-0.325) 6(-2.95,-0.975) 7(-2.95,-1.625) 8(-2.95,-2.275) 9(2.95,-2.275) 10(2.95,-1.625) 11(2.95,-0.975) 12(2.95,-0.325) 13(2.95,0.325) 14(2.95,0.975) 15(2.95,1.625) 16(2.95,2.275)
  silkscreen extent -3.5,-2.55 1.85,2.75, body extent -3.21,-2.5 3.21,2.5, height 1
RQS0052C-C01-MFG [mm]
  rrect9% 1.15x1.1 smd paste+0 mask+0: 1(-5.725,5.2) 16(-5.725,-5.2) 27(5.725,-5.2) 42(5.725,5.2)
  rrect22% 1.15x0.45 smd paste+0 mask+0: 2(-5.725,4.225) 3(-5.725,3.575) 4(-5.725,2.925) 5(-5.725,2.275) 6(-5.725,1.625) 7(-5.725,0.975) 8(-5.725,0.325) 9(-5.725,-0.325) 10(-5.725,-0.975) 11(-5.725,-1.625) 12(-5.725,-2.275) 13(-5.725,-2.925) 14(-5.725,-3.575) 15(-5.725,-4.225) 28(5.725,-4.225) 29(5.725,-3.575) 30(5.725,-2.925) 31(5.725,-2.275) 32(5.725,-1.625) 33(5.725,-0.975) 34(5.725,-0.325) 35(5.725,0.325) 36(5.725,0.975) 37(5.725,1.625) 38(5.725,2.275) 39(5.725,2.925) 40(5.725,3.575) 41(5.725,4.225)
  rrect15% 0.665x1.15 smd paste+0 mask+0: 17(-2.043,-5.725) 52(-2.043,5.725)
  rrect22% 0.45x1.15 smd paste+0 mask+0: 18(-1.285,-5.725) 19(-0.635,-5.725) 20(0.015,-5.725) 21(0.665,-5.725) 22(1.315,-5.725) 23(1.965,-5.725) 24(2.615,-5.725) 25(3.265,-5.725) 26(3.915,-5.725) 43(3.915,5.725) 44(3.265,5.725) 45(2.615,5.725) 46(1.965,5.725) 47(1.315,5.725) 48(0.665,5.725) 49(0.015,5.725) 50(-0.635,5.725) 51(-1.285,5.725)
  silkscreen extent -7.02,-6.05 4.77,6.05, body extent -6,-6 6,6, height 1
SMA [mm] "Molded Diode, 2-Leads, Body 4.3x2.6mm, IPC Medium Density, based on OnSemi component dimensions and land pattern"
  rect 2x2 smd: 1(-2,0) 2(2,0)
  silkscreen extent -3.66,-1.57 2.79,1.57, body extent -2.6,-1.3 2.6,1.3, height 2.42
SMAF [mm] "SMD, 2-Leads, Body 3.8x2.5mm"
  rect 1.24x1.89 smd: 1(-2.04,0) 2(2.04,0)
  silkscreen extent -3.4,-1.3 2.8,1.3, body extent -2.35,-1.25 2.35,1.25, height 1
SMC [mil] "Molded Diode, 2-Leads, Body 6.9x5.8mm, IPC Medium Density, based on OnSemi component dimensions and land patterns"
  rect 110x150 smd: 1(-140.49,0) 2(140.49,0)
  silkscreen extent -221,-123 189,124, body extent -156,-116 156,116, height 91
SOD-123 [mm] "On Semi recommended land pattern"
  rect 0.915x1.22 smd: 1(-1.637,0) 2(1.637,0)
  silkscreen extent -2.74,-1.17 2.03,1.17, body extent -1.93,-0.9 1.93,0.9, height 1.35
SRN3015 [mm] "SMD, 2-Leads, Body 3x3mm"
  rect 1x2.7 smd: 1(-1.1,0) 2(1.1,0)
  silkscreen extent -0.5,-1.7 0.5,1.7
TNPV1206 [mm] "VISHAY"
  rrect11% 0.9x1.7 smd: 1(-1.6,0) 2(1.6,0)
  silkscreen extent -2.4,-1.2 2.4,1.2, body extent -1.67,-0.87 1.67,0.87, height 0.65
UWT_630x770 [mm] "SMD, 2-Leads, Dia 6.3mm"
  rrect6% 3.5x1.6 smd: 1(-2.7,0) 2(2.7,0)
  body extent -3.5,-3.3 3.5,3.3, height 8
WEEE_Minimum [mm] "WEEElie bin"
  silkscreen extent -2.42,-4.38 2.52,2.65
WURTH_61300211121 [mm] "Header, 2.54mm, 2x1, TH"
  rrect50% 1.65x1.65 hole 1.15: 1(-1.27,0)
  round 1.65 hole 1.15: 2(1.27,0)
  body extent -2.54,-1.27 2.54,1.27, height 8.54
Wurth_618009231121 [mm] "Receptacle, D-Sub, 9 Position, R/A, TH"
  rect 1.5x1.5 hole 1: 1(-10.92,5.54)
  round 1.5 hole 1: 2(-10.92,2.77) 3(-10.92,0) 4(-10.92,-2.77) 5(-10.92,-5.54) 6(-8.08,4.155) 7(-8.08,1.385) 8(-8.08,-1.385) 9(-8.08,-4.155)
  round 3.7 hole 3.2: 10(-9.5,12.5) 11(-9.5,-12.5)
  silkscreen extent -12.78,-15.4 -0.53,15.4, body extent -12.5,-15.4 6,15.4, height 12.5
Wurth_WP-THRBU [mm] "Power Element Bush, M3, TH"
  round 3.2 hole 1.85: 1(-2.935,-2.935) 1(-2.935,2.935) 1(2.935,-2.935) 1(2.935,2.935)
  round 3.1 on Top Paste: ""(-2.935,-2.935) ""(-2.935,2.935) ""(2.935,-2.935) ""(2.935,2.935)
  round 3 hole 3.3 unplated mask+0.102: ""(0,0)
  silkscreen extent -3.5,-3.5 3.5,3.5, body extent -3.5,-3.5 3.5,3.5, height 3

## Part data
C1: library part CMP-0086078-1, "CAP, CERM, 2200 pF, 3000 V,+/- 10%, B, Dia 12.5mm", Cap_Case=12.5x6x16.5mm, Manufacturer=TDK, TempCo=B, Tolerance_%=10%, Value2=3000V, ValueDisplayed=2200pF
C2 C3 C4 C5: library part CMP-0033686-1, "ALH82, Aluminum Electrolytic, 160 uF, 20%, 600 VDC, -40/+105°C", Leakage Current=288uA, Manufacturer=KEMET, Operating Temperature Range="-40°C to +105°C", Tolerance_%=20%, ValueDisplayed=160uF
C6 C45 C56 C74 C75: library part CMP-0007225-4, "CAP, CERM, 560 pF, 50 V, +/- 5%, C0G/NP0, 0603", Cap_Case=0603, Manufacturer=MuRata, Supplier Part Number 1=490-1445-1-ND, TempCo=C0G/NP0, Tolerance_%=5%, Value1=Unknown, Value2=50V, ValueDisplayed=560pF
C7 C8 C9 C143 C144 C148 C155 C160: library part CMP-0007194-4, "CAP, CERM, 200 pF, 50 V, +/- 5%, C0G/NP0, 0603", Cap_Case=0603, Manufacturer=MuRata, Supplier Part Number 1=490-1434-1-ND, TempCo=C0G/NP0, Tolerance_%=5%, Value1=Unknown, Value2=50V, ValueDisplayed=200pF
C10 C16 C22 C25 C29 C38 C39 C43 C44 C47 C50 C55 C62 C67 C70 C85 C91 C95 C114 C125 C127 C169 C176 C182 C185 C186 C201 C203: library part CMP-0006752-5, "CAP, CERM, 0.1 uF, 25 V, +/- 5%, X7R, 0603", Cap_Case=0603, Manufacturer=AVX, Supplier Part Number 1=478-3713-1-ND, TempCo=X7R, Tolerance_%=5%, Value1="0.05 ohm", Value2=25V, ValueDisplayed=0.1uF
C11 C24 C49 C57 C69 C94: library part CMP-0750154-1, "CAP, CERM, 10 µF, 25 V,+/- 10%, X7R, AEC-Q200 Grade 1, 1206", Cap_Case=1206, Manufacturer="Taiyo Yuden", TempCo=X7R, Tolerance_%=10%, Value2=25V, ValueDisplayed=10µF
C12 C58: library part CMP-0007389-4, "CAP, CERM, 0.22 uF, 16 V, +/- 10%, X7R, 0603", Cap_Case=0603, Manufacturer=MuRata, Supplier Part Number 1=490-3293-1-ND, TempCo=X7R, Tolerance_%=10%, Value1=Unknown, Value2=16V, ValueDisplayed=0.22uF
C13 C26 C51 C59 C71: library part CMP-0006921-4, "CAP, CERM, 330 pF, 50 V, +/- 10%, X7R, 0603", Cap_Case=0603, Manufacturer=Kemet, Supplier Part Number 1=399-1073-1-ND, TempCo=X7R, Tolerance_%=10%, Value1=Unknown, Value2=50V, ValueDisplayed=330pF
C14 C27 C32 C33 C34 C35 C36 C37 C41 C42 C48 C52 C53 C60 C72 C77 C78 C79 C80 C82 C83 C86 C87 C89 C92 C93 C96 C97 C98 C101 C107 C108 C112 C113 C130 C131 C132 C133 C134 C135 C136 C137 C145 C151 C152 C157 C163 C164 C167 C168 C170 C171 C172 C173 C174 C175 C177 C178 C179 C180 C190 C192 C193 C194 C196 C199 C200 C202 C204 C206 C208 C209 C218 C219 C231 C232 C234 C235 C245 C246 C247 C248 C249 C250 C253 C254 C255 C256: library part CMP-0007442-5, "CAP, CERM, 220 pF, 50 V, +/- 10%, X7R, 0603", Cap_Case=0603, Manufacturer=MuRata, Supplier Part Number 1=490-1483-1-ND, TempCo=X7R, Tolerance_%=10%, Value1=Unknown, Value2=50V, ValueDisplayed=220pF
C15 C28 C54 C61 C73 C99: library part CMP-0007975-2, "CAP, CERM, 2.2 uF, 25 V, +/- 10%, X7R, AEC-Q200 Grade 1, 0805", Cap_Case=0805, Manufacturer=TDK, Supplier Part Number 1=445-6965-1-ND, TempCo=X7R, Tolerance_%=10%, Value1=Unknown, Value2=25V, ValueDisplayed=2.2uF
C17 C63 C111 C119 C122 C123 C181 C189 C198 C210 C211 C214 C223 C226: library part CMP-0086152-1, "CAP, CERM, 1 µF, 25 V,+/- 10%, X5R, 0603", Cap_Case=0603, Manufacturer="Taiyo Yuden", TempCo=X5R, Tolerance_%=10%, Value2=25V, ValueDisplayed=1µF
C18 C64: library part CMP-0009474-2, "CAP, CERM, 20 uF, 16 V, +/- 20%, X5R, 0704", Cap_Case=0704, Manufacturer=MuRata, TempCo=X5R, Tolerance_%=20%, Value1=Unknown, Value2=16V, ValueDisplayed=20uF
C19 C20 C65 C120 C121 C124 C126 C188: library part CMP-0094458-1, "10µF ±20% 25V Ceramic Capacitor X5R 0603 (1608 Metric)", Digikey Part Number=490-10991-1-ND, Manufacturer="Murata Electronics", Mouser Part Number=81-ZRB18AR61E106ME1L, Operating Temperature Range="-55°C to +85°C", Temperature Characteristic=X5R, Tolerance_%=20%, ValueDisplayed=10uF
C21 C66: library part CMP-0007209-4, "CAP, CERM, 330 pF, 50 V, +/- 5%, C0G/NP0, 0603", Cap_Case=0603, Manufacturer=MuRata, Supplier Part Number 1=490-1439-1-ND, TempCo=C0G/NP0, Tolerance_%=5%, Value1=Unknown, Value2=50V, ValueDisplayed=330pF
C23 C68 C110: library part CMP-0750039-1, "CAP, CERM, 0.01 µF, 50 V,+/- 10%, X7R, 0603", Cap_Case=0603, Manufacturer="Wurth Elektronik", TempCo=X7R, Tolerance_%=10%, Value2=50V, ValueDisplayed=0.01µF
C30 C31 C46 C76 C88 C90 C229: library part CMP-0009326-2, "CAP, CERM, 0.1 uF, 1000 V, +/- 10%, X7R, 1812", Cap_Case=1812, Manufacturer=Kemet, Supplier Part Number 1=399-6523-1-ND, TempCo=X7R, Tolerance_%=10%, Value1=Unknown, Value2=1000V, ValueDisplayed=0.1uF
C40 C238 C239 C240 C251 C252: library part CMP-0081462-1, "CAP, AL, 100 µF, 25 V, +/- 20%, SMD", Cap_Case=6.3x7.7mm, Manufacturer=Nichicon, Supplier Part Number 1=493-2190-1-ND, Tolerance_%=20%, Value2=25V, ValueDisplayed=100µF
C81 C100 C150 C154 C156 C159 C162 C166: library part CMP-0007195-4, "CAP, CERM, 2000 pF, 50 V, +/- 5%, C0G/NP0, 0603", Cap_Case=0603, Manufacturer=MuRata, Supplier Part Number 1=490-1458-1-ND, TempCo=C0G/NP0, Tolerance_%=5%, Value1=Unknown, Value2=50V, ValueDisplayed=2000pF
C84: library part CMP-0006837-4, "CAP, CERM, 0.1 uF, 50 V, +/- 10%, X7R, 0603", Cap_Case=0603, Manufacturer="Wurth Elektronik", TempCo=X7R, Tolerance_%=10%, Value1=Unknown, Value2=50V, ValueDisplayed=0.1uF
C102 C106: library part CMP-0042924-1, "6800 pF Film Capacitor 300V 1500V (1.5kV) Polypropylene (PP), Metallized Radial", Digikey Part Number=399-R413F168050T0K-ND, Manufacturer=KEMET, Mouser Part Number=80-R413F168050T0K, Operating Temperature Range="-40°C to +125°C", Tolerance_%=10%, ValueDisplayed=6800pF, Voltage Ac Rating Y=300V
C103 C104: library part CMP-0038396-1, "4.7 µF Film Capacitor 310V 630V Polypropylene (PP), Metallized Radial", Digikey Part Number=399-F862FY475K310ZV054-ND, Manufacturer=KEMET, Mouser Part Number=80-F862FY475K31ZV054, Operating Temperature Range="-40°C to +110°C", Tolerance_%=10%, ValueDisplayed=4.7uF, Voltage Ac Rating X=310V
C105 C109 C115: library part CMP-0007470-5, "CAP, CERM, 0.1 uF, 100 V, +/- 10%, X7R, 0603", Cap_Case=0603, Manufacturer=MuRata, Supplier Part Number 1=490-6439-1-ND, TempCo=X7R, Tolerance_%=10%, Value1=Unknown, Value2=100V, ValueDisplayed=0.1uF
C116: library part CMP-0010555-2, "CAP, AL, 10 uF, 35 V, +/- 20%, TH", Cap_Case=5x11, Manufacturer=Nichicon, Supplier Part Number 1=UVR1V100MDD1TA-ND, Tolerance_%=20%, Value1=Unknown, Value2=35V, ValueDisplayed=10uF
C117: library part CMP-0006775-4, "CAP, CERM, 22 pF, 50 V, +/- 5%, C0G/NP0, 0603", Cap_Case=0603, Manufacturer=AVX, Supplier Part Number 1=478-1167-1-ND, TempCo=C0G/NP0, Tolerance_%=5%, Value1="0.259 ohm", Value2=50V, ValueDisplayed=22pF
C118: library part CMP-0010348-1, "CAP, AL, 150 uF, 25 V, +/- 20%, TH", Cap_Case=6.3x11.2mm, Manufacturer=Panasonic, Supplier Part Number 1=P15352CT-ND, Tolerance_%=20%, Value1=Unknown, Value2=25V, ValueDisplayed=150uF
C128 C141 C142 C161 C165 C230: library part CMP-0006979-5, "CAP, CERM, 0.1 uF, 25 V, +/- 10%, X7R, 0603", Cap_Case=0603, Manufacturer=Kemet, Supplier Part Number 1=399-5345-1-ND, TempCo=X7R, Tolerance_%=10%, Value1=Unknown, Value2=25V, ValueDisplayed=0.1uF
C129 C138: library part CMP-0006840-4, "CAP, CERM, 100 pF, 50 V, +/- 5%, C0G/NP0, 0603", Cap_Case=0603, Manufacturer=Kemet, Supplier Part Number 1=1414602, TempCo=C0G/NP0, Tolerance_%=5%, Value1=Unknown, Value2=50V, ValueDisplayed=100pF
C146 C158: library part CMP-0006953-4, "CAP, CERM, 560 pF, 50 V, +/- 5%, C0G/NP0, 0603", Cap_Case=0603, Manufacturer=Kemet, Supplier Part Number 1=399-3287-1-ND, TempCo=C0G/NP0, Tolerance_%=5%, Value1=Unknown, Value2=50V, ValueDisplayed=560pF
C191 C207 C213 C215 C225 C228: library part CMP-0008310-2, "CAP, CERM, 10 uF, 35 V, +/- 10%, X5R, 0805", Cap_Case=0805, Manufacturer=MuRata, Supplier Part Number 1=490-10514-1-ND, TempCo=X5R, Tolerance_%=10%, Value1=Unknown, Value2=35V, ValueDisplayed=10uF
C195 C197 C205 C216 C222 C224: library part CMP-0085850-1, "CAP, CERM, 0.1 µF, 16 V,+/- 10%, X7R, 0402", Cap_Case=0402, Manufacturer=Walsin, TempCo=X7R, Tolerance_%=10%, Value2=16V, ValueDisplayed=0.1µF
C212 C227: library part CMP-0085842-1, "CAP, CERM, 0.01 µF, 50 V,+/- 10%, X7R, 0402", Cap_Case=0402, Manufacturer=Walsin, TempCo=X7R, Tolerance_%=10%, Value2=50V, ValueDisplayed=0.01µF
